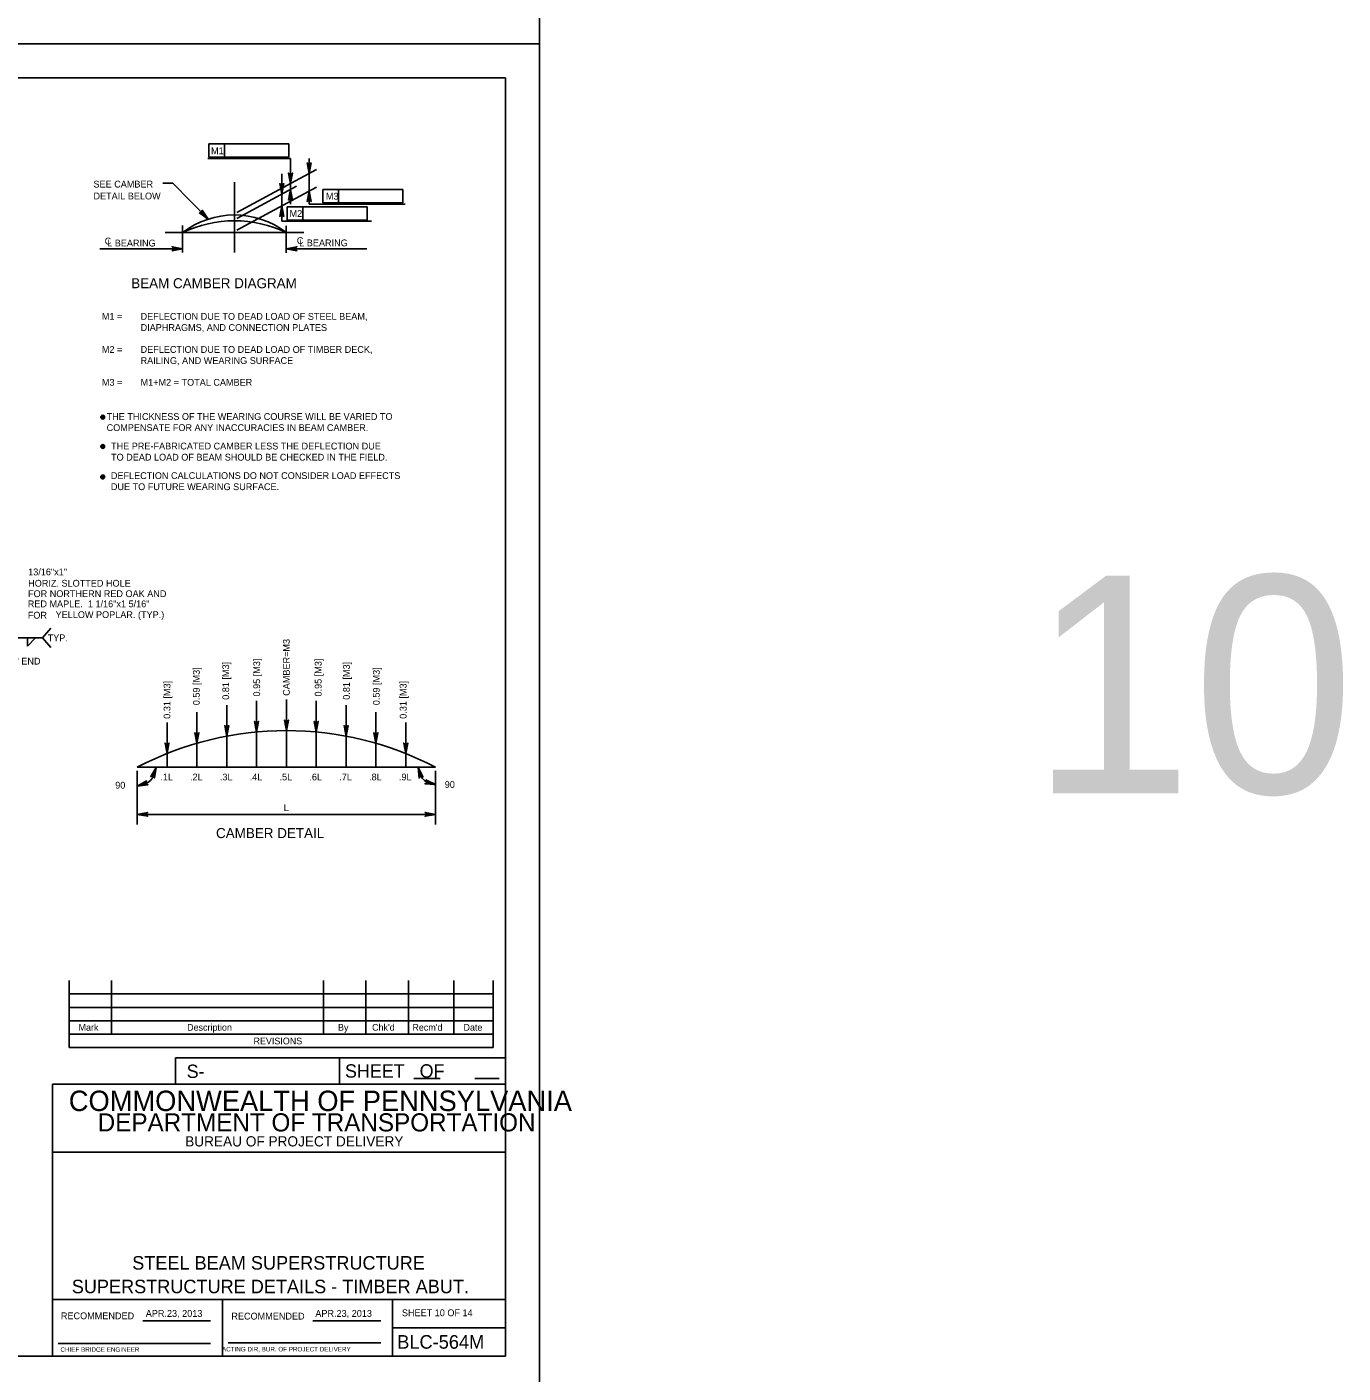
# Model space of a CAD drawing. Extents: x 638175 to 640495, y 294277 to 298435.
# Drawn here: x 639891 to 640472, y 296661 to 297255 of the extents above; entities that cross this region are included whole.
import ezdxf

# ---------------------------------------------------------------- set-up
doc = ezdxf.new("R2010")
doc.units = 0
for name, color, linetype in [('1', 7, 'Continuous'), ('2', 7, 'Continuous'), ('3', 7, 'Continuous'), ('4', 7, 'Continuous'), ('5', 7, 'Continuous'), ('53', 7, 'Continuous'), ('6', 7, 'Continuous'), ('PLT-BNDY', 7, 'Continuous')]:
    doc.layers.add(name, color=color, linetype=linetype)

msp = doc.modelspace()

# ---------------------------------------------------------------- linework, layer by layer
at = {"layer": '2'}
for p, q in [((639316.46, 297232.46), (640102.46, 297232.46)), ((640102.46, 297232.46), (640102.46, 296668.46)), ((639909.92, 296834.15), (639909.92, 296804.62)), ((639928.62, 296834.15), (639928.62, 296810.53)), ((640022.13, 296834.15), (640022.13, 296810.53)), ((640040.83, 296834.15), (640040.83, 296810.53)), ((640059.53, 296834.15), (640059.53, 296810.53)), ((640079.59, 296834.15), (640079.59, 296810.53)), ((640096.94, 296834.15), (640096.94, 296804.62)), ((640096.94, 296828.24), (639909.92, 296828.24)), ((640096.94, 296822.34), (639909.92, 296822.34)), ((640096.94, 296816.43), (639909.92, 296816.43)), ((640096.94, 296810.53), (639909.92, 296810.53)), ((640096.94, 296804.62), (639909.92, 296804.62)), ((640102.46, 296800.11), (639956.78, 296800.11)), ((639956.78, 296800.11), (639956.78, 296788.46)), ((640029.09, 296800.11), (640029.09, 296788.46)), ((640102.46, 296788.46), (639902.46, 296788.46)), ((639902.46, 296788.46), (639902.46, 296668.46)), ((640061.95, 296791), (640073.6, 296791)), ((640088.83, 296791), (640099.56, 296791)), ((640102.46, 296758.46), (639902.46, 296758.46)), ((640102.46, 296693.46), (639902.46, 296693.46)), ((639977.46, 296668.46), (639977.46, 296693.46)), ((640052.46, 296693.46), (640052.46, 296668.46)), ((639942.42, 296683.96), (639972.19, 296683.96)), ((640017.42, 296683.96), (640047.33, 296683.96)), ((640052.46, 296680.96), (640102.46, 296680.96)), ((639904.96, 296673.96), (639972.19, 296673.96)), ((639980.08, 296674.33), (640047.33, 296674.33)), ((640102.46, 296668.46), (639316.46, 296668.46))]:
    msp.add_line(p, q, dxfattribs=at)
at = {"layer": '3'}
for p, q in [((639971.56, 297203.39), (640006.86, 297203.39)), ((639971.56, 297197.48), (639971.56, 297203.39)), ((639978.45, 297197.48), (639978.45, 297203.39)), ((640006.86, 297203.39), (640006.86, 297197.48)), ((640007.49, 297196.9), (639971, 297196.9)), ((640006.86, 297197.48), (639971.56, 297197.48)), ((640007.49, 297196.9), (640007.49, 297176.78)), ((640015.76, 297186.3), (640015.76, 297196.9)), ((639983.87, 297173.05), (640019.05, 297192.05)), ((640003.69, 297169.19), (640003.69, 297190.12)), ((639955.65, 297186.06), (639951.15, 297186.06)), ((639971.2, 297170.14), (639955.65, 297186.06)), ((639982.81, 297155.49), (639982.81, 297186.43)), ((639983.87, 297170.46), (640010.2, 297184.69)), ((639983.87, 297165.29), (640019.05, 297184.3)), ((640015.76, 297186.3), (640015.76, 297176.78)), ((640021.82, 297183.23), (640057.12, 297183.23)), ((640021.82, 297177.32), (640021.82, 297183.23)), ((640028.71, 297177.32), (640028.71, 297183.23)), ((640057.12, 297183.23), (640057.12, 297177.32)), ((640006.09, 297175.61), (640041.39, 297175.61)), ((640006.09, 297169.71), (640006.09, 297175.61)), ((640012.98, 297169.71), (640012.98, 297175.61)), ((640058.13, 297176.78), (640015.76, 297176.78)), ((640057.12, 297177.32), (640021.82, 297177.32)), ((640041.39, 297175.61), (640041.39, 297169.71)), ((639959.93, 297167.27), (639959.93, 297155.35)), ((640043.2, 297169.19), (640003.69, 297169.19)), ((640005.69, 297167.14), (640005.69, 297155.22)), ((640041.39, 297169.71), (640006.09, 297169.71)), ((639959.93, 297157.09), (639923.45, 297157.09)), ((640005.69, 297157.09), (640041.25, 297157.09)), ((639898.14, 296985.39), (639901.85, 296989.59)), ((639874.4, 296985.39), (639898.14, 296985.39)), ((639891.56, 296985.39), (639891.56, 296981.72)), ((639891.56, 296981.72), (639895.09, 296985.39)), ((639898.14, 296985.39), (639901.85, 296981.19)), ((639966.21, 296938.85), (639966.21, 296952.56)), ((639979.38, 296942), (639979.38, 296955.71)), ((639992.55, 296943.85), (639992.55, 296957.56)), ((640005.71, 296944.46), (640005.71, 296958.17)), ((640018.88, 296943.85), (640018.88, 296957.56)), ((640032.05, 296942), (640032.05, 296955.71)), ((640045.21, 296938.85), (640045.21, 296952.56)), ((639953.05, 296934.32), (639953.05, 296948.03)), ((640058.38, 296934.32), (640058.38, 296948.03)), ((639939.88, 296926.7), (639939.88, 296903)), ((640071.55, 296926.7), (640071.55, 296903)), ((639939.88, 296907.5), (640071.55, 296907.5))]:
    msp.add_line(p, q, dxfattribs=at)
for points in [[(640007.49, 297185.8), (640006.62, 297190.46), (640006.87, 297190.11), (640007.18, 297189.92), (640007.49, 297189.87), (640007.81, 297189.92), (640008.12, 297190.11), (640008.37, 297190.46), (640007.49, 297185.8), (640008.12, 297190.11), (640007.81, 297189.92), (640007.49, 297185.8), (640007.49, 297189.87), (640007.18, 297189.92), (640007.49, 297185.8), (640006.87, 297190.11)], [(640015.76, 297190.27), (640014.89, 297194.93), (640015.14, 297194.57), (640015.45, 297194.39), (640015.76, 297194.33), (640016.07, 297194.39), (640016.39, 297194.57), (640016.63, 297194.93), (640015.76, 297190.27), (640016.39, 297194.57), (640016.07, 297194.39), (640015.76, 297190.27), (640015.76, 297194.33), (640015.45, 297194.39), (640015.76, 297190.27), (640015.14, 297194.57)], [(640003.69, 297181.17), (640002.82, 297185.83), (640003.07, 297185.47), (640003.38, 297185.29), (640003.69, 297185.23), (640004.01, 297185.29), (640004.32, 297185.47), (640004.57, 297185.83), (640003.69, 297181.17), (640004.32, 297185.47), (640004.01, 297185.29), (640003.69, 297181.17), (640003.69, 297185.23), (640003.38, 297185.29), (640003.69, 297181.17), (640003.07, 297185.47)], [(640007.49, 297183.22), (640008.37, 297178.56), (640008.12, 297178.92), (640007.81, 297179.1), (640007.49, 297179.16), (640007.18, 297179.1), (640006.87, 297178.92), (640006.62, 297178.56), (640007.49, 297183.22), (640006.87, 297178.92), (640007.18, 297179.1), (640007.49, 297183.22), (640007.49, 297179.16), (640007.81, 297179.1), (640007.49, 297183.22), (640008.12, 297178.92)], [(640015.76, 297182.52), (640016.63, 297177.86), (640016.39, 297178.22), (640016.07, 297178.4), (640015.76, 297178.46), (640015.45, 297178.4), (640015.14, 297178.22), (640014.89, 297177.86), (640015.76, 297182.52), (640015.14, 297178.22), (640015.45, 297178.4), (640015.76, 297182.52), (640015.76, 297178.46), (640016.07, 297178.4), (640015.76, 297182.52), (640016.39, 297178.22)], [(639971.2, 297170.14), (639967.31, 297172.87), (639967.74, 297172.78), (639968.1, 297172.87), (639968.36, 297173.05), (639968.54, 297173.31), (639968.64, 297173.66), (639968.56, 297174.09), (639971.2, 297170.14), (639968.64, 297173.66), (639968.54, 297173.31), (639971.2, 297170.14), (639968.36, 297173.05), (639968.1, 297172.87), (639971.2, 297170.14), (639967.74, 297172.78)], [(640003.69, 297176), (640004.57, 297171.34), (640004.32, 297171.7), (640004.01, 297171.88), (640003.69, 297171.94), (640003.38, 297171.88), (640003.07, 297171.7), (640002.82, 297171.34), (640003.69, 297176), (640003.07, 297171.7), (640003.38, 297171.88), (640003.69, 297176), (640003.69, 297171.94), (640004.01, 297171.88), (640003.69, 297176), (640004.32, 297171.7)], [(639959.93, 297157.09), (639955.27, 297156.22), (639955.62, 297156.47), (639955.81, 297156.78), (639955.86, 297157.09), (639955.81, 297157.41), (639955.62, 297157.72), (639955.27, 297157.97), (639959.93, 297157.09), (639955.62, 297157.72), (639955.81, 297157.41), (639959.93, 297157.09), (639955.86, 297157.09), (639955.81, 297156.78), (639959.93, 297157.09), (639955.62, 297156.47)], [(640005.69, 297157.09), (640010.35, 297157.97), (640010, 297157.72), (640009.81, 297157.41), (640009.76, 297157.09), (640009.81, 297156.78), (640010, 297156.47), (640010.35, 297156.22), (640005.69, 297157.09), (640010, 297156.47), (640009.81, 297156.78), (640005.69, 297157.09), (640009.76, 297157.09), (640009.81, 297157.41), (640005.69, 297157.09), (640010, 297157.72)], [(639979.38, 296942), (639978.51, 296946.66), (639978.76, 296946.3), (639979.07, 296946.11), (639979.38, 296946.06), (639979.69, 296946.11), (639980.01, 296946.3), (639980.25, 296946.66), (639979.38, 296942), (639980.01, 296946.3), (639979.69, 296946.11), (639979.38, 296942), (639979.38, 296946.06), (639979.07, 296946.11), (639979.38, 296942), (639978.76, 296946.3)], [(639992.55, 296943.85), (639991.67, 296948.51), (639991.92, 296948.15), (639992.24, 296947.97), (639992.55, 296947.91), (639992.86, 296947.97), (639993.17, 296948.15), (639993.42, 296948.51), (639992.55, 296943.85), (639993.17, 296948.15), (639992.86, 296947.97), (639992.55, 296943.85), (639992.55, 296947.91), (639992.24, 296947.97), (639992.55, 296943.85), (639991.92, 296948.15)], [(640005.71, 296944.46), (640004.84, 296949.12), (640005.09, 296948.76), (640005.4, 296948.58), (640005.71, 296948.52), (640006.03, 296948.58), (640006.34, 296948.76), (640006.59, 296949.12), (640005.71, 296944.46), (640006.34, 296948.76), (640006.03, 296948.58), (640005.71, 296944.46), (640005.71, 296948.52), (640005.4, 296948.58), (640005.71, 296944.46), (640005.09, 296948.76)], [(640018.88, 296943.85), (640018.01, 296948.51), (640018.26, 296948.15), (640018.57, 296947.97), (640018.88, 296947.91), (640019.19, 296947.97), (640019.51, 296948.15), (640019.75, 296948.51), (640018.88, 296943.85), (640019.51, 296948.15), (640019.19, 296947.97), (640018.88, 296943.85), (640018.88, 296947.91), (640018.57, 296947.97), (640018.88, 296943.85), (640018.26, 296948.15)], [(640032.05, 296942), (640031.17, 296946.66), (640031.42, 296946.3), (640031.74, 296946.11), (640032.05, 296946.06), (640032.36, 296946.11), (640032.67, 296946.3), (640032.92, 296946.66), (640032.05, 296942), (640032.67, 296946.3), (640032.36, 296946.11), (640032.05, 296942), (640032.05, 296946.06), (640031.74, 296946.11), (640032.05, 296942), (640031.42, 296946.3)], [(639966.21, 296938.85), (639965.34, 296943.51), (639965.59, 296943.15), (639965.9, 296942.97), (639966.21, 296942.91), (639966.53, 296942.97), (639966.84, 296943.15), (639967.09, 296943.51), (639966.21, 296938.85), (639966.84, 296943.15), (639966.53, 296942.97), (639966.21, 296938.85), (639966.21, 296942.91), (639965.9, 296942.97), (639966.21, 296938.85), (639965.59, 296943.15)], [(640045.21, 296938.85), (640044.34, 296943.51), (640044.59, 296943.15), (640044.9, 296942.97), (640045.21, 296942.91), (640045.53, 296942.97), (640045.84, 296943.15), (640046.09, 296943.51), (640045.21, 296938.85), (640045.84, 296943.15), (640045.53, 296942.97), (640045.21, 296938.85), (640045.21, 296942.91), (640044.9, 296942.97), (640045.21, 296938.85), (640044.59, 296943.15)], [(639953.05, 296934.32), (639952.17, 296938.98), (639952.42, 296938.63), (639952.74, 296938.44), (639953.05, 296938.39), (639953.36, 296938.44), (639953.67, 296938.63), (639953.92, 296938.98), (639953.05, 296934.32), (639953.67, 296938.63), (639953.36, 296938.44), (639953.05, 296934.32), (639953.05, 296938.39), (639952.74, 296938.44), (639953.05, 296934.32), (639952.42, 296938.63)], [(640058.38, 296934.32), (640057.51, 296938.98), (640057.76, 296938.63), (640058.07, 296938.44), (640058.38, 296938.39), (640058.69, 296938.44), (640059.01, 296938.63), (640059.25, 296938.98), (640058.38, 296934.32), (640059.01, 296938.63), (640058.69, 296938.44), (640058.38, 296934.32), (640058.38, 296938.39), (640058.07, 296938.44), (640058.38, 296934.32), (640057.76, 296938.63)], [(639948.21, 296928.24), (639947.49, 296923.56), (639947.38, 296923.98), (639947.14, 296924.26), (639946.87, 296924.41), (639946.55, 296924.46), (639946.2, 296924.39), (639945.84, 296924.14), (639948.21, 296928.24), (639946.2, 296924.39), (639946.55, 296924.46), (639948.21, 296928.24), (639946.87, 296924.41), (639947.14, 296924.26), (639948.21, 296928.24), (639947.38, 296923.98)], [(640063.9, 296928.26), (640065.96, 296923.99), (640065.62, 296924.27), (640065.27, 296924.36), (640064.96, 296924.33), (640064.67, 296924.2), (640064.42, 296923.94), (640064.27, 296923.53), (640063.9, 296928.26), (640064.42, 296923.94), (640064.67, 296924.2), (640063.9, 296928.26), (640064.96, 296924.33), (640065.27, 296924.36), (640063.9, 296928.26), (640065.62, 296924.27)], [(639939.89, 296919.96), (639944.05, 296922.24), (639943.79, 296921.89), (639943.71, 296921.53), (639943.75, 296921.22), (639943.9, 296920.94), (639944.17, 296920.7), (639944.59, 296920.58), (639939.89, 296919.96), (639944.17, 296920.7), (639943.9, 296920.94), (639939.89, 296919.96), (639943.75, 296921.22), (639943.71, 296921.53), (639939.89, 296919.96), (639943.79, 296921.89)], [(640071.54, 296920.61), (640066.82, 296921.03), (640067.23, 296921.17), (640067.49, 296921.42), (640067.63, 296921.71), (640067.66, 296922.02), (640067.57, 296922.37), (640067.29, 296922.71), (640071.54, 296920.61), (640067.57, 296922.37), (640067.66, 296922.02), (640071.54, 296920.61), (640067.63, 296921.71), (640067.49, 296921.42), (640071.54, 296920.61), (640067.23, 296921.17)], [(639939.88, 296907.5), (639944.54, 296908.37), (639944.18, 296908.13), (639944, 296907.81), (639943.94, 296907.5), (639944, 296907.19), (639944.18, 296906.88), (639944.54, 296906.63), (639939.88, 296907.5), (639944.18, 296906.88), (639944, 296907.19), (639939.88, 296907.5), (639943.94, 296907.5), (639944, 296907.81), (639939.88, 296907.5), (639944.18, 296908.13)], [(640071.55, 296907.5), (640066.89, 296906.63), (640067.25, 296906.88), (640067.43, 296907.19), (640067.49, 296907.5), (640067.43, 296907.81), (640067.25, 296908.13), (640066.89, 296908.37), (640071.55, 296907.5), (640067.25, 296908.13), (640067.43, 296907.81), (640071.55, 296907.5), (640067.49, 296907.5), (640067.43, 296907.19), (640071.55, 296907.5), (640067.25, 296906.88)]]:
    msp.add_lwpolyline(points, dxfattribs=at)
for points in [[(640016.25, 297193.22), (640015.27, 297193.22), (640015.76, 297190.27)], [(640007.99, 297188.76), (640007, 297188.76), (640007.49, 297185.8)], [(640004.19, 297184.12), (640003.2, 297184.12), (640003.69, 297181.17)], [(640007, 297180.27), (640007.99, 297180.27), (640007.49, 297183.22)], [(640015.27, 297179.57), (640016.25, 297179.57), (640015.76, 297182.52)], [(639968.59, 297173.89), (639967.51, 297172.84), (639971.2, 297170.14)], [(640003.2, 297173.05), (640004.19, 297173.05), (640003.69, 297176)], [(639956.97, 297156.6), (639956.97, 297157.59), (639959.93, 297157.09)], [(640008.65, 297156.6), (640008.65, 297157.59), (640005.69, 297157.09)], [(639993.05, 296946.85), (639992.05, 296946.85), (639992.55, 296943.85)], [(640006.21, 296947.46), (640005.21, 296947.46), (640005.71, 296944.46)], [(640019.38, 296946.85), (640018.38, 296946.85), (640018.88, 296943.85)], [(639966.71, 296941.85), (639965.71, 296941.85), (639966.21, 296938.85)], [(639979.88, 296945), (639978.88, 296945), (639979.38, 296942)], [(640032.55, 296945), (640031.55, 296945), (640032.05, 296942)], [(640045.71, 296941.85), (640044.71, 296941.85), (640045.21, 296938.85)], [(639953.55, 296937.32), (639952.55, 296937.32), (639953.05, 296934.32)], [(640058.88, 296937.32), (640057.88, 296937.32), (640058.38, 296934.32)], [(639942.88, 296908), (639942.88, 296907), (639939.88, 296907.5)], [(640068.55, 296908), (640068.55, 296907), (640071.55, 296907.5)]]:
    msp.add_lwpolyline(points, close=True, dxfattribs=at)
for centre, radius in [((639924.66, 297082.74), 0.833), ((639924.66, 297082.74), 0.417), ((639924.66, 297069.81), 0.833), ((639924.66, 297069.81), 0.417), ((639924.66, 297056.38), 0.833), ((639924.66, 297056.38), 0.417)]:
    msp.add_circle(centre, radius, dxfattribs=at)
for centre, radius, start, end in [((639939.88, 296928.26), 8.24, 269.99961, 359.99852), ((640071.55, 296928.26), 7.62, 180.0016, 270.00489)]:
    msp.add_arc(centre, radius, start, end, dxfattribs=at)
at = {"layer": '5'}
for p, q in [((639979.38, 296942), (639979.38, 296928.26)), ((639992.55, 296943.85), (639992.55, 296928.26)), ((640005.71, 296944.46), (640005.71, 296928.26)), ((640018.88, 296943.85), (640018.88, 296928.26)), ((640032.05, 296942), (640032.05, 296928.26)), ((639966.21, 296938.85), (639966.21, 296928.26)), ((640045.21, 296938.85), (640045.21, 296928.26)), ((639953.05, 296934.32), (639953.05, 296928.26)), ((640058.38, 296934.32), (640058.38, 296928.26)), ((639953.05, 296928.26), (639953.05, 296928.26)), ((639966.21, 296928.26), (639966.21, 296928.26)), ((639979.38, 296928.26), (639979.38, 296928.26)), ((639992.55, 296928.26), (639992.55, 296928.26)), ((640005.71, 296928.26), (640005.71, 296928.26)), ((640018.88, 296928.26), (640018.88, 296928.26)), ((640032.05, 296928.26), (640032.05, 296928.26)), ((640045.21, 296928.26), (640045.21, 296928.26)), ((640058.38, 296928.26), (640058.38, 296928.26))]:
    msp.add_line(p, q, dxfattribs=at)
for centre, radius, start, end in [((639982.81, 297134.32), 37.66, 52.57653, 127.42348), ((639982.81, 297116.14), 53.26, 64.55129, 115.44871), ((640005.71, 296802.6), 141.86, 62.35093, 117.64907)]:
    msp.add_arc(centre, radius, start, end, dxfattribs=at)
at = {"layer": '6'}
for p, q in [((639952.16, 297164.23), (640013.46, 297164.23)), ((639939.88, 296928.26), (640071.55, 296928.26))]:
    msp.add_line(p, q, dxfattribs=at)
at = {"layer": 'PLT-BNDY'}
for points in [[(639276.46, 297841.46), (640117.46, 297841.46), (640117.46, 297247.46), (639276.46, 297247.46)], [(639276.46, 297247.46), (640117.46, 297247.46), (640117.46, 296653.46), (639276.46, 296653.46)]]:
    msp.add_lwpolyline(points, close=True, dxfattribs=at)

# ---------------------------------------------------------------- texts
at = {"layer": '1'}
msp.add_text('SHEET 10 OF 14', height=3, dxfattribs=at).set_placement((640056.68, 296686.06))
at = {"layer": '2'}
for s, height, p in [('Mark', 2.952, (639914.02, 296812.03)), ('Description', 2.9523, (639961.92, 296812.03)), ('By', 2.952, (640028.49, 296812.03)), ("Chk'd", 2.952, (640043.52, 296812.03)), ("Recm'd", 2.953, (640061.33, 296812.03)), ('Date', 2.952, (640083.86, 296812.03)), ('REVISIONS', 2.952, (639991.2, 296806.01)), ('S-', 5.905, (639961.73, 296791.17)), ('COMMONWEALTH OF PENNSYLVANIA', 9, (639909.71, 296776.58)), ('DEPARTMENT OF TRANSPORTATION', 8.0002, (639922.46, 296767.58)), ('BUREAU OF PROJECT DELIVERY', 4.5, (639961.05, 296760.96)), ('SUPERSTRUCTURE DETAILS - TIMBER ABUT.', 5.9714, (639911.02, 296696.18)), ('APR.23, 2013', 3, (639943.67, 296685.77)), ('APR.23, 2013', 3, (640018.48, 296685.77)), ('BLC-564M', 6, (640054.64, 296671.71)), ('CHIEF BRIDGE ENGINEER', 2.0002, (639906.05, 296670.33)), ('  ACTING DIR, BUR. OF PROJECT DELIVERY', 2.0002, (639975.78, 296670.51))]:
    msp.add_text(s, height=height, dxfattribs=at).set_placement(p)
for s, height, p in [('SHEET   OF', 5.907, (640031.58, 296791.31)), ('RECOMMENDED', 3, (639906.23, 296684.71)), ('RECOMMENDED', 3, (639981.44, 296684.58))]:
    msp.add_text(s, height=height, rotation=360, dxfattribs=at).set_placement(p)
at = {"layer": '3'}
for s, height, p in [('M1', 3, (639972.47, 297198.78)), ('SEE CAMBER', 3, (639920.59, 297184.09)), ('DETAIL BELOW', 3, (639920.59, 297178.84)), ('M3', 3, (640023.15, 297178.75)), ('M2', 3, (640007.13, 297171.14)), ('C', 3, (639925.55, 297158.97)), ('L BEARING', 3, (639926.65, 297158.07)), ('C', 3, (640010.31, 297159.16)), ('L BEARING', 3, (640011.38, 297158.16)), ('BEAM CAMBER DIAGRAM', 4.4292, (639937.26, 297139.65)), ('M1 =', 3, (639924.31, 297125.72)), ('DEFLECTION DUE TO DEAD LOAD OF STEEL BEAM,', 3, (639941.39, 297125.72)), ('DIAPHRAGMS, AND CONNECTION PLATES', 3, (639941.39, 297120.82)), ('M2 =', 3, (639924.31, 297111.13)), ('DEFLECTION DUE TO DEAD LOAD OF TIMBER DECK,', 3, (639941.39, 297111.13)), ('RAILING, AND WEARING SURFACE', 3, (639941.39, 297106.23)), ('M3 =', 3, (639924.31, 297096.63)), ('M1+M2 = TOTAL CAMBER', 3, (639941.39, 297096.63)), (' THE THICKNESS OF THE WEARING COURSE WILL BE VARIED TO', 3, (639925.29, 297081.54)), (' COMPENSATE FOR ANY INACCURACIES IN BEAM CAMBER.', 3, (639925.29, 297076.64)), ('THE PRE-FABRICATED CAMBER LESS THE DEFLECTION DUE', 3, (639928.36, 297068.5)), ('TO DEAD LOAD OF BEAM SHOULD BE CHECKED IN THE FIELD.', 3, (639928.36, 297063.6)), ('DEFLECTION CALCULATIONS DO NOT CONSIDER LOAD EFFECTS', 3, (639928.28, 297055.46)), ('DUE TO FUTURE WEARING SURFACE.', 3, (639928.28, 297050.57)), ('13/16"x1"', 3, (639891.79, 297012.97)), ('FOR NORTHERN RED OAK AND', 3, (639891.72, 297003.36)), ('HORIZ. SLOTTED HOLE', 3, (639891.79, 297007.97)), ('RED MAPLE.  1 1/16"x1 5/16"', 3, (639891.61, 296998.88)), ('FOR ', 3, (639891.61, 296993.88)), ('YELLOW POPLAR. (TYP.)', 3, (639903.89, 296994.11)), ('TYP.', 3, (639900.39, 296983.89)), ('1/2" END  ', 3, (639880.65, 296973.59)), ('.1L', 3, (639950.11, 296922.48)), ('.2L', 3, (639963.19, 296922.48)), ('.3L', 3, (639976.36, 296922.48)), ('.4L', 3, (639989.53, 296922.48)), ('.5L', 3, (640002.69, 296922.48)), ('.6L', 3, (640015.86, 296922.48)), ('.7L', 3, (640029.03, 296922.48)), ('.8L', 3, (640042.19, 296922.48)), ('.9L', 3, (640055.36, 296922.48)), ('90', 3, (639930.19, 296918.85)), ('90', 3, (640075.58, 296919.18)), ('L', 3, (640004.55, 296908.97)), ('CAMBER DETAIL', 4.4292, (639974.68, 296897.02))]:
    msp.add_text(s, height=height, dxfattribs=at).set_placement(p)
for s, p in [('CAMBER=M3', (640007.21, 296959.8)), ('0.59 [M3]', (639967.5, 296955.66)), ('0.81 [M3]', (639980.45, 296958.06)), ('0.95 [M3]', (639994.12, 296959.5)), ('0.95 [M3]', (640021.25, 296959.5)), ('0.81 [M3]', (640033.71, 296958.06)), ('0.59 [M3]', (640046.9, 296955.66)), ('0.31 [M3]', (639954.55, 296949.66)), ('0.31 [M3]', (640058.74, 296949.66))]:
    msp.add_text(s, height=3, rotation=90, dxfattribs=at).set_placement(p)
at = {"layer": '4'}
msp.add_text('STEEL BEAM SUPERSTRUCTURE', height=5.9714, dxfattribs=at).set_placement((639937.69, 296706.61))
at = {"layer": '53'}
msp.add_text('10', height=96, dxfattribs=at).set_placement((640334.16, 296916.8))

doc.saveas('drawing.dxf')
